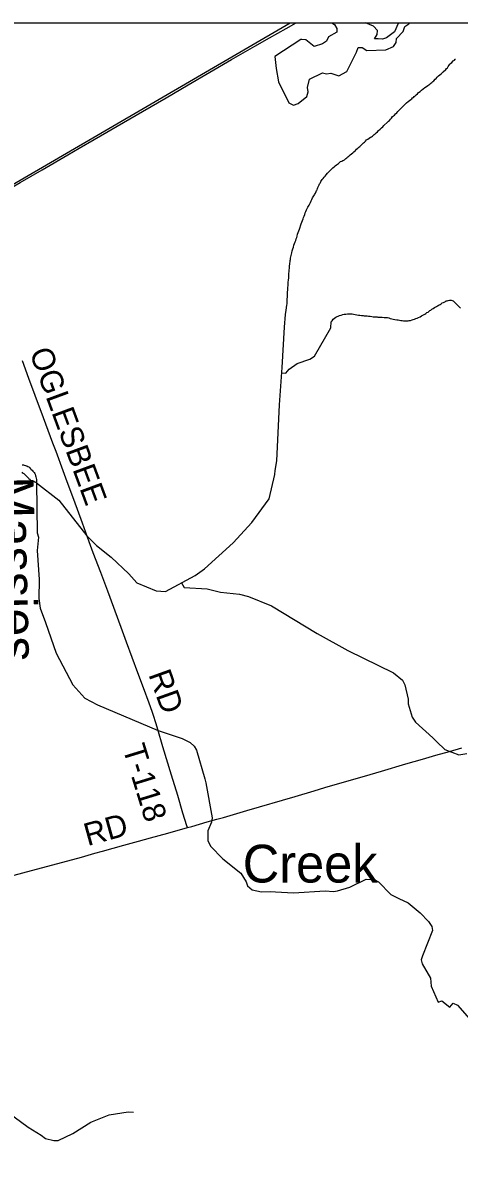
# Model space of a CAD drawing. Extents: x -49 to -8.2, y 9.4 to 23.5.
# Drawn here: x -11.894 to -11.348, y 14.781 to 16.209 of the extents above; entities that cross this region are included whole.
import ezdxf

# ---------------------------------------------------------------- set-up
doc = ezdxf.new("R2010")
doc.units = 0
for name, color, linetype in [('GM_X_Adjacent_County', 7, 'Continuous'), ('GM_X_County_Road', 7, 'Continuous'), ('GM_X_County_Road_Text', 7, 'Continuous'), ('GM_X_Minor_Lake', 7, 'Continuous'), ('GM_X_Minor_River', 7, 'Continuous'), ('GM_X_Minor_River_Text', 7, 'Continuous'), ('GM_X_Township', 7, 'Continuous'), ('GM_X_Township_Road', 7, 'Continuous'), ('GM_X_Township_Road_Text', 7, 'Continuous')]:
    doc.layers.add(name, color=color, linetype=linetype)

msp = doc.modelspace()

# ---------------------------------------------------------------- linework, layer by layer
at = {"layer": 'GM_X_Adjacent_County'}
msp.add_lwpolyline([(-14.9662, 16.2087), (-8.1662, 16.2087), (-8.1662, 9.4087), (-14.9662, 9.4087)], close=True, dxfattribs=at)
at = {"layer": 'GM_X_County_Road'}
for points in [[(-11.9639, 15.97), (-11.9575, 15.9738), (-11.9414, 15.9832), (-11.918, 15.9967), (-11.8979, 16.0084), (-11.8702, 16.0245), (-11.838, 16.0433), (-11.8238, 16.0516), (-11.8052, 16.0623), (-11.7681, 16.0839), (-11.7445, 16.0976), (-11.7149, 16.1148), (-11.6873, 16.1308), (-11.6327, 16.1625), (-11.6155, 16.1725), (-11.6035, 16.1795), (-11.5851, 16.19), (-11.5645, 16.2016), (-11.552, 16.2087)], [(-11.688, 15.2), (-11.6827, 15.2015), (-11.6633, 15.2071), (-11.6514, 15.2105), (-11.643, 15.2129), (-11.6135, 15.2215), (-11.553, 15.2392), (-11.5294, 15.2463), (-11.5161, 15.2503), (-11.4913, 15.2574), (-11.4662, 15.2646), (-11.445, 15.2708), (-11.4143, 15.2798), (-11.3934, 15.2858), (-11.377, 15.2907), (-11.3597, 15.2956), (-11.3442, 15.3)], [(-11.9979, 15.1151), (-11.9839, 15.1191), (-11.9599, 15.1257), (-11.9372, 15.1321), (-11.8945, 15.1434), (-11.8648, 15.1512), (-11.8504, 15.155), (-11.8207, 15.163), (-11.804, 15.1678), (-11.7944, 15.1705), (-11.7677, 15.1779), (-11.7495, 15.1829), (-11.7342, 15.1872), (-11.7126, 15.193), (-11.688, 15.2)]]:
    msp.add_lwpolyline(points, dxfattribs=at)
at = {"layer": 'GM_X_Minor_Lake'}
for points in [[(-11.5771, 16.1514), (-11.5742, 16.1348), (-11.561, 16.1084), (-11.5552, 16.1056), (-11.5495, 16.1074), (-11.5384, 16.1164), (-11.5368, 16.1221), (-11.5376, 16.1276), (-11.5353, 16.1382), (-11.519, 16.1458), (-11.5139, 16.1446), (-11.5085, 16.1456), (-11.4985, 16.1422), (-11.4885, 16.1478), (-11.4764, 16.1719), (-11.4742, 16.1775), (-11.4693, 16.1778), (-11.4634, 16.1741), (-11.4395, 16.1749), (-11.4299, 16.1788), (-11.4265, 16.1839), (-11.4262, 16.1888), (-11.4177, 16.1978), (-11.4155, 16.2038), (-11.4106, 16.2075), (-11.4097, 16.2087)], [(-11.5072, 16.2087), (-11.5038, 16.2066), (-11.5009, 16.2014), (-11.501, 16.1967), (-11.5112, 16.191), (-11.5138, 16.1858), (-11.519, 16.1823), (-11.5293, 16.1789), (-11.5396, 16.1871), (-11.5447, 16.1879), (-11.5461, 16.1876)], [(-11.4237, 16.2087), (-11.4239, 16.2078), (-11.4285, 16.1974), (-11.4386, 16.19), (-11.4435, 16.1882), (-11.4489, 16.1886), (-11.4538, 16.1887), (-11.4505, 16.1941), (-11.4498, 16.199), (-11.455, 16.2046), (-11.4649, 16.2087)], [(-11.5461, 16.1876), (-11.5784, 16.1666), (-11.5771, 16.1514)]]:
    msp.add_lwpolyline(points, dxfattribs=at)
at = {"layer": 'GM_X_Minor_River'}
for points in [[(-11.5071, 16.0255), (-11.5058, 16.0268), (-11.5044, 16.0282), (-11.5029, 16.0295), (-11.5015, 16.0306), (-11.5002, 16.0315), (-11.499, 16.0324), (-11.4977, 16.0335), (-11.4961, 16.0347), (-11.4946, 16.0354), (-11.4934, 16.0361), (-11.4923, 16.0365), (-11.4913, 16.0371), (-11.4896, 16.0384), (-11.4884, 16.0395), (-11.4871, 16.0406), (-11.4857, 16.0417), (-11.484, 16.0432), (-11.4824, 16.0445), (-11.4809, 16.0458), (-11.4795, 16.0471), (-11.4776, 16.0488), (-11.4761, 16.0503), (-11.4747, 16.0516), (-11.4734, 16.0527), (-11.4722, 16.0538), (-11.471, 16.0549), (-11.4697, 16.0561), (-11.4685, 16.0572), (-11.4674, 16.0581), (-11.4662, 16.0592), (-11.4649, 16.0603), (-11.4637, 16.0618), (-11.462, 16.063), (-11.4602, 16.0641), (-11.4587, 16.0652), (-11.4573, 16.0659), (-11.4562, 16.0667), (-11.4552, 16.0676), (-11.4541, 16.0685), (-11.4529, 16.0694), (-11.4515, 16.0708), (-11.45, 16.0722), (-11.4485, 16.0736), (-11.4465, 16.0754), (-11.445, 16.0769), (-11.4434, 16.0784), (-11.4419, 16.0799), (-11.4374, 16.0842), (-11.4363, 16.0853), (-11.4349, 16.0864), (-11.4336, 16.0877), (-11.4324, 16.089), (-11.431, 16.0913), (-11.4287, 16.0928), (-11.4272, 16.0945), (-11.4258, 16.096), (-11.4245, 16.0973), (-11.4231, 16.0986), (-11.4219, 16.0999), (-11.4206, 16.1012), (-11.4194, 16.1025), (-11.4182, 16.1038), (-11.4169, 16.1051), (-11.4155, 16.1064), (-11.4136, 16.1083), (-11.4117, 16.11), (-11.4099, 16.1113), (-11.4082, 16.1124), (-11.407, 16.1135), (-11.4059, 16.1144), (-11.4049, 16.1152), (-11.4038, 16.1161), (-11.4026, 16.1172), (-11.4014, 16.1185), (-11.3999, 16.1198), (-11.3985, 16.1213), (-11.3966, 16.1226), (-11.3949, 16.1243), (-11.3927, 16.126), (-11.3906, 16.1275), (-11.3885, 16.1289), (-11.3868, 16.1301), (-11.3856, 16.131), (-11.3845, 16.1317), (-11.3831, 16.1328), (-11.3818, 16.134), (-11.3806, 16.1349), (-11.3793, 16.136), (-11.3777, 16.1379), (-11.3765, 16.139), (-11.3752, 16.1405), (-11.3736, 16.142), (-11.3719, 16.1435), (-11.3703, 16.1448), (-11.3688, 16.1461), (-11.3676, 16.147), (-11.3644, 16.1502), (-11.3634, 16.1513), (-11.3624, 16.1524), (-11.3614, 16.1539)], [(-11.3614, 16.1539), (-11.3603, 16.1554), (-11.3591, 16.1566), (-11.3583, 16.1575), (-11.3568, 16.159), (-11.355, 16.1609), (-11.3535, 16.162), (-11.3527, 16.1629), (-11.3521, 16.1631)], [(-11.5663, 15.8271), (-11.5652, 15.843), (-11.5643, 15.8485), (-11.5635, 15.8549), (-11.5633, 15.8565), (-11.563, 15.858), (-11.563, 15.8599), (-11.563, 15.8625), (-11.5629, 15.8646), (-11.5629, 15.8663), (-11.5629, 15.8675), (-11.5629, 15.8686), (-11.5627, 15.8699), (-11.5626, 15.8715), (-11.5624, 15.8734), (-11.5622, 15.8758), (-11.5622, 15.8773), (-11.5619, 15.8792), (-11.5617, 15.8811), (-11.5617, 15.8838), (-11.5614, 15.8863), (-11.5612, 15.8889), (-11.561, 15.8912), (-11.5609, 15.8931), (-11.5609, 15.895), (-11.5607, 15.8967), (-11.5606, 15.899), (-11.5604, 15.9009), (-11.5604, 15.9026), (-11.5602, 15.9041), (-11.56, 15.906), (-11.5599, 15.9075), (-11.5595, 15.9092), (-11.5593, 15.9109), (-11.5591, 15.9122), (-11.5589, 15.9138), (-11.5585, 15.9153), (-11.5583, 15.917), (-11.5574, 15.9204), (-11.5568, 15.923), (-11.556, 15.9253), (-11.5554, 15.9276), (-11.5546, 15.9298), (-11.5538, 15.9319), (-11.5532, 15.934), (-11.5524, 15.9359), (-11.5518, 15.938), (-11.551, 15.9397), (-11.5506, 15.9414), (-11.55, 15.9436), (-11.5492, 15.9457), (-11.5486, 15.948), (-11.5478, 15.9501), (-11.5454, 15.9565), (-11.5448, 15.9586), (-11.544, 15.961), (-11.5432, 15.9631), (-11.5426, 15.9648), (-11.542, 15.9663), (-11.5412, 15.9686), (-11.5404, 15.9703), (-11.5396, 15.9721), (-11.5388, 15.9742), (-11.5379, 15.9759), (-11.5371, 15.9774), (-11.5363, 15.9787), (-11.5357, 15.9802), (-11.5349, 15.9819), (-11.5339, 15.9836), (-11.5329, 15.9855), (-11.5321, 15.9874), (-11.5314, 15.9891), (-11.5304, 15.9906), (-11.5296, 15.9919), (-11.529, 15.993), (-11.5284, 15.994), (-11.5278, 15.9951), (-11.5272, 15.9961), (-11.5266, 15.9972), (-11.5262, 15.9983), (-11.5257, 15.9995), (-11.5251, 16.0008), (-11.5245, 16.0021), (-11.5243, 16.003), (-11.5237, 16.004), (-11.5231, 16.0057), (-11.5225, 16.0068), (-11.5219, 16.0077), (-11.5215, 16.0087), (-11.5209, 16.0096), (-11.5199, 16.0111), (-11.5192, 16.0124), (-11.518, 16.0136), (-11.5166, 16.0151), (-11.5155, 16.0166), (-11.5141, 16.0183), (-11.5124, 16.0201), (-11.5083, 16.0242), (-11.5071, 16.0255)], [(-11.5085, 15.8265), (-11.508, 15.8337), (-11.5069, 15.8353), (-11.5053, 15.8372), (-11.504, 15.8383), (-11.502, 15.8398), (-11.4974, 15.8418), (-11.4953, 15.8424), (-11.4932, 15.8429), (-11.4915, 15.8433), (-11.4898, 15.8436), (-11.4875, 15.8439), (-11.486, 15.8439), (-11.4846, 15.8439), (-11.4831, 15.8439), (-11.4816, 15.8438), (-11.4799, 15.8436), (-11.4778, 15.8432), (-11.4757, 15.8428), (-11.4738, 15.8424), (-11.4719, 15.8422), (-11.47, 15.8419), (-11.4679, 15.8417), (-11.4666, 15.8415), (-11.4647, 15.8413), (-11.463, 15.8412), (-11.4611, 15.841), (-11.459, 15.8408), (-11.4569, 15.8406), (-11.4552, 15.8403), (-11.4537, 15.8403), (-11.452, 15.8401), (-11.4504, 15.8401), (-11.4495, 15.8399), (-11.4476, 15.8398), (-11.4459, 15.8398), (-11.444, 15.8398), (-11.4417, 15.8395), (-11.4394, 15.8395), (-11.4373, 15.8393), (-11.4356, 15.8387), (-11.4339, 15.8381), (-11.4318, 15.8377), (-11.4301, 15.8374), (-11.4284, 15.837), (-11.4257, 15.8364), (-11.424, 15.8362), (-11.4223, 15.8358), (-11.4208, 15.8356), (-11.4189, 15.8355), (-11.4172, 15.8353), (-11.4157, 15.8351), (-11.4138, 15.8353), (-11.4122, 15.8352), (-11.4113, 15.8352), (-11.4103, 15.8354), (-11.4084, 15.8357), (-11.4065, 15.8363), (-11.4052, 15.8366), (-11.4036, 15.8372), (-11.4019, 15.8379), (-11.4002, 15.8386), (-11.3985, 15.8394), (-11.3965, 15.8403), (-11.3946, 15.8414), (-11.3921, 15.8425), (-11.3906, 15.8434), (-11.3892, 15.8443), (-11.3879, 15.8455), (-11.3866, 15.846), (-11.3852, 15.8471), (-11.3842, 15.8479), (-11.3831, 15.8486), (-11.3817, 15.8497), (-11.3802, 15.8506), (-11.3786, 15.8519), (-11.3769, 15.8525), (-11.3758, 15.8532), (-11.3746, 15.854), (-11.3737, 15.8545), (-11.3727, 15.8553), (-11.3715, 15.8558), (-11.3702, 15.8565), (-11.3687, 15.8575), (-11.3673, 15.858), (-11.3664, 15.8586), (-11.3648, 15.8595), (-11.3637, 15.86), (-11.3627, 15.8604), (-11.3614, 15.8608), (-11.3598, 15.8611), (-11.3589, 15.8611), (-11.3576, 15.8611), (-11.3553, 15.8601), (-11.3538, 15.8589), (-11.3525, 15.8576), (-11.3502, 15.8552), (-11.3482, 15.8529), (-11.3461, 15.851)], [(-11.8773, 15.6323), (-11.8491, 15.6103), (-11.814, 15.5658), (-11.8021, 15.5536), (-11.7836, 15.539), (-11.7614, 15.5181), (-11.7516, 15.5067), (-11.7275, 15.4966), (-11.7156, 15.496), (-11.6783, 15.516), (-11.6666, 15.5245), (-11.631, 15.5571), (-11.6074, 15.5825), (-11.5856, 15.6119), (-11.5785, 15.6427), (-11.578, 15.6477), (-11.5759, 15.6598), (-11.5726, 15.7298), (-11.5693, 15.7766), (-11.5663, 15.8271)], [(-11.5697, 15.7699), (-11.5648, 15.7695), (-11.5608, 15.7744), (-11.5506, 15.7816), (-11.5348, 15.7872), (-11.529, 15.7907), (-11.5085, 15.8265)], [(-11.8952, 15.6548), (-11.8937, 15.6546), (-11.8926, 15.6542), (-11.8912, 15.6538), (-11.8903, 15.6535), (-11.8894, 15.6533), (-11.8882, 15.6527), (-11.8869, 15.6521), (-11.8858, 15.6511), (-11.8846, 15.6498), (-11.8839, 15.6488), (-11.8828, 15.6479), (-11.8818, 15.6469), (-11.8809, 15.6459), (-11.8803, 15.645), (-11.8794, 15.6438), (-11.879, 15.6429), (-11.8785, 15.641), (-11.8781, 15.6396), (-11.8776, 15.6379), (-11.8774, 15.6364), (-11.8772, 15.6353), (-11.8772, 15.6339), (-11.8772, 15.6322), (-11.8782, 15.6326), (-11.8793, 15.6328), (-11.8808, 15.6336), (-11.8822, 15.634), (-11.8833, 15.6346), (-11.8846, 15.6352), (-11.8854, 15.6363), (-11.8863, 15.6365), (-11.8867, 15.6375), (-11.8878, 15.6384), (-11.8887, 15.6392), (-11.8901, 15.6409), (-11.8912, 15.6417), (-11.8927, 15.6434), (-11.8942, 15.6444), (-11.8953, 15.6455)], [(-11.8772, 15.6322), (-11.8763, 15.5694), (-11.8749, 15.5642), (-11.8763, 15.5472), (-11.8739, 15.511), (-11.8745, 15.4871), (-11.8725, 15.4749), (-11.8658, 15.4572), (-11.8525, 15.4188), (-11.8316, 15.3791), (-11.8169, 15.3621), (-11.8007, 15.3538), (-11.7246, 15.3219), (-11.6948, 15.3118), (-11.6847, 15.3065), (-11.6795, 15.3019), (-11.6767, 15.2969), (-11.6665, 15.261), (-11.6651, 15.256), (-11.657, 15.2122), (-11.6578, 15.2067), (-11.6626, 15.1958), (-11.6626, 15.184), (-11.6593, 15.1767), (-11.6439, 15.1611), (-11.6213, 15.143), (-11.6144, 15.1319), (-11.613, 15.1269), (-11.6068, 15.1222), (-11.5951, 15.1197), (-11.5842, 15.1201), (-11.5779, 15.1196), (-11.5554, 15.1184), (-11.5154, 15.1209), (-11.5051, 15.1198), (-11.5, 15.121), (-11.4846, 15.1253), (-11.4643, 15.1354), (-11.4543, 15.135), (-11.4488, 15.1321), (-11.4332, 15.1162), (-11.4231, 15.1111), (-11.4116, 15.1059), (-11.3965, 15.0933), (-11.3862, 15.0825), (-11.382, 15.0763), (-11.3808, 15.0712), (-11.3936, 15.0395), (-11.3952, 15.0344), (-11.3938, 15.0291), (-11.3837, 15.0112), (-11.3826, 15.0013), (-11.374, 14.9814), (-11.3693, 14.9829), (-11.3593, 14.9751), (-11.3549, 14.9799), (-11.3495, 14.9776), (-11.3316, 14.9569)], [(-11.6955, 15.5068), (-11.6922, 15.5009), (-11.6634, 15.4992), (-11.6468, 15.4949), (-11.6228, 15.4924), (-11.6117, 15.4896), (-11.5827, 15.478), (-11.5254, 15.4435), (-11.4869, 15.4218), (-11.4298, 15.3939), (-11.4184, 15.3846), (-11.4155, 15.3791), (-11.4116, 15.3608), (-11.4117, 15.3551), (-11.4065, 15.3383), (-11.4021, 15.3321), (-11.3806, 15.3125), (-11.3756, 15.3077), (-11.3654, 15.2978), (-11.348, 15.2912), (-11.3378, 15.2927)], [(-11.9134, 14.8436), (-11.8878, 14.8245), (-11.8715, 14.8145), (-11.8659, 14.8106), (-11.8557, 14.808), (-11.8502, 14.8081), (-11.8317, 14.8166), (-11.8091, 14.8308), (-11.7862, 14.8401), (-11.7626, 14.8437), (-11.7556, 14.8434)]]:
    msp.add_lwpolyline(points, dxfattribs=at)
at = {"layer": 'GM_X_Township'}
msp.add_lwpolyline([(-12.8378, 15.0202), (-12.6759, 15.1194), (-12.4401, 15.2545), (-12.6216, 15.5669), (-12.433, 15.6794), (-12.4382, 15.6895), (-12.3543, 15.7412), (-12.1972, 15.8377), (-11.9664, 15.9718), (-11.5592, 16.2087)], dxfattribs=at)
at = {"layer": 'GM_X_Township_Road'}
msp.add_lwpolyline([(-11.688, 15.2), (-11.6888, 15.2024), (-11.6937, 15.2181), (-11.7002, 15.2402), (-11.708, 15.2657), (-11.7188, 15.3011), (-11.7254, 15.3228), (-11.7275, 15.33), (-11.7287, 15.334), (-11.7299, 15.338), (-11.7311, 15.3416), (-11.7324, 15.3454), (-11.7361, 15.3559), (-11.7433, 15.3754), (-11.7501, 15.3941), (-11.7644, 15.4325), (-11.7712, 15.4509), (-11.788, 15.4964), (-11.7967, 15.5197), (-11.8061, 15.5443), (-11.8112, 15.5582), (-11.8196, 15.5817), (-11.8259, 15.5986), (-11.8318, 15.6147), (-11.8387, 15.6333), (-11.8438, 15.647), (-11.8528, 15.6715), (-11.8567, 15.682), (-11.8685, 15.7137), (-11.8789, 15.7417), (-11.8867, 15.7627), (-11.8948, 15.7848)], dxfattribs=at)

# ---------------------------------------------------------------- texts
at = {"layer": 'GM_X_County_Road_Text'}
msp.add_text('RD', height=0.02841, rotation=15.4755, dxfattribs=at).set_placement((-11.8133, 15.1767))
at = {"layer": 'GM_X_Minor_River_Text'}
for s, height, rotation, p in [('Massies', 0.04734, 271.3636, (-11.9285, 15.6396)), ('Creek', 0.04735, 359.998, (-11.6188, 15.1312))]:
    msp.add_text(s, height=height, rotation=rotation, dxfattribs=at).set_placement(p)
at = {"layer": 'GM_X_Township_Road_Text'}
for s, rotation, p in [('OGLESBEE', 290.2436, (-11.8865, 15.7958)), ('RD', 289.6876, (-11.7373, 15.392)), ('T-118', 287.1024, (-11.7696, 15.2998))]:
    msp.add_text(s, height=0.02841, rotation=rotation, dxfattribs=at).set_placement(p)

doc.saveas('drawing.dxf')
